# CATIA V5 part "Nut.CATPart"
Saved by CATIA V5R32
Part number: Nut
Bounding box of the stored display mesh (mm): x -86.603 to 86.603, y -100 to 100, z 0 to 50
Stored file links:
  D:\PROJECTS\Project 2022\CATIA V5 6R 2022\Resources\Part Files\c16_catia_v5_6r2022_prt\Screw Joint-(Fig16-22)\Nut.CATPart
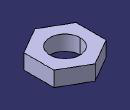
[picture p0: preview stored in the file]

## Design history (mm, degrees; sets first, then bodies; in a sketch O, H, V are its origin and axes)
Body1 (main body)
  Sketch1 on xy-plane, origin (0, 0, 0), H (1, 0, 0), V (0, 1, 0)
    point P1 (86.6025, -50)
    point P2 (86.6025, 50)
    point P3 (0, 100)
    point P4 (-86.6025, 50)
    point P5 (-86.6025, -50)
    point P6 (0, -100)
    point P7 (86.6025, 0)
    line L1 (86.6025, -50) -> (86.6025, 50)
    line L2 (86.6025, 50) -> (0, 100)
    line L3 (0, 100) -> (-86.6025, 50)
    line L4 (-86.6025, 50) -> (-86.6025, -50)
    line L5 (-86.6025, -50) -> (0, -100)
    line L6 (0, -100) -> (86.6025, -50)
    construction line L7 (0, 0) -> (86.6025, 0)
    construction circle A1 centre (0, 0) radius 100
    construction arc A2 centre (-86.6025, -50) radius 100 from (-86.6025, 50) to (0, -100) cw
    construction arc A3 centre (86.6025, 50) radius 100 from (0, 100) to (86.6025, -50) ccw
    circle A4 centre (0, 0) radius 50
    radius A1 = 100
    radius A4 = 50
    horizontal: L7 H
    coincidence: A1 P1, A1 P2, A1 P3, A1 P4, A1 P5, A1 P6, A2 O, A3 O
    midpoint: P7 L1
    parallelism: L1 L4, L2 L5, L3 L6
    vertical: L4 V, L1 V
  Pad1: profile Sketch1, direction (0, 0, 1), length 50
  Thread1: diameter 100, depth 50, pitch 1, on face of Pad1 from Sketch1.A4, from end face of Pad1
